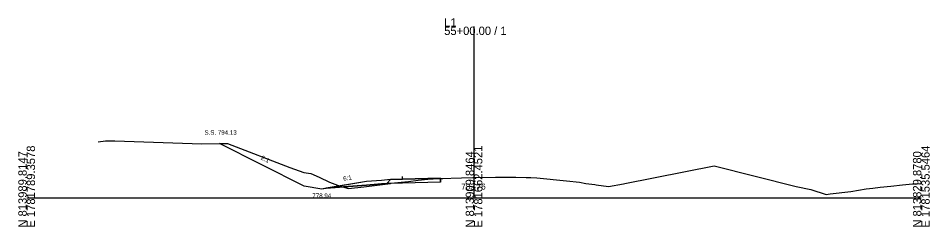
# Model space of a CAD drawing. Extents: x 5574 to 10203, y -10 to 9546.
# Drawn here: x 6597.2 to 6902.8, y 1990.3 to 2060.1 of the extents above; entities that cross this region are included whole.
import ezdxf

# ---------------------------------------------------------------- set-up
doc = ezdxf.new("R2010")
doc.units = 0
for name, color, linetype in [('Exist Cross Section Cell', 7, 'Continuous'), ('Exist XS Center Line Elevation Label', 7, 'Continuous'), ('Exist XS Ground Line', 7, 'Continuous'), ('Prop XS Ditch Slope Text', 7, 'Continuous'), ('Prop XS Ditch Standard Text', 7, 'Continuous'), ('Prop XS Dump Level', 7, 'Continuous'), ('Prop XS Earthwork Shape', 7, 'Continuous'), ('Prop XS EOT Tick Mark', 7, 'Continuous'), ('Prop XS Finish Grade', 7, 'Continuous'), ('Prop XS Finish Grade Earthwork', 7, 'Continuous'), ('Prop XS Finish Grade Paved Shoulder', 7, 'Continuous'), ('Prop XS Finish Grade Pavement', 7, 'Continuous'), ('Prop XS Hydro Typical Ditch Data', 7, 'Continuous'), ('Prop XS Pvmt Edge Slope', 7, 'Continuous'), ('Prop XS Side Slope Text', 7, 'Continuous'), ('Prop XS SS Elevation Text', 7, 'Continuous'), ('Prop XS Subgrade Earthwork', 7, 'Continuous'), ('Scratch_Level_3', 7, 'Continuous'), ('Scratch_Level_6', 7, 'Continuous')]:
    doc.layers.add(name, color=color, linetype=linetype)

msp = doc.modelspace()

# ---------------------------------------------------------------- linework, layer by layer
at = {"layer": 'Exist Cross Section Cell'}
for p, q in [((6750, 2000), (6750, 2057.31)), ((6600, 2000), (6750, 2000)), ((6750, 2000), (6900, 2000))]:
    msp.add_line(p, q, dxfattribs=at)
at = {"layer": 'Exist XS Ground Line'}
for p, q in [((6624.02, 2018.79), (6626.44, 2019.02)), ((6626.44, 2019.02), (6629.55, 2019.1)), ((6629.55, 2019.1), (6658.7, 2018.11)), ((6658.7, 2018.11), (6667.32, 2018.14)), ((6667.32, 2018.14), (6688.26, 2010.11)), ((6688.26, 2010.11), (6692.91, 2008.43)), ((6692.91, 2008.43), (6695.27, 2008.18)), ((6800.59, 2004.76), (6830.57, 2010.73)), ((6830.57, 2010.73), (6858.02, 2003.79)), ((6695.27, 2008.18), (6698.13, 2006.88)), ((6698.13, 2006.88), (6701.51, 2005.23)), ((6725.57, 2005.2), (6728.05, 2005.47)), ((6728.05, 2005.47), (6731.24, 2005.86)), ((6731.24, 2005.86), (6734.54, 2006.27)), ((6734.54, 2006.27), (6736.32, 2006.37)), ((6736.32, 2006.37), (6738.75, 2006.49)), ((6738.75, 2006.49), (6745.83, 2006.66)), ((6745.83, 2006.66), (6750, 2006.76)), ((6750, 2006.76), (6750.85, 2006.78)), ((6750.85, 2006.78), (6757.19, 2006.86)), ((6757.19, 2006.86), (6761.9, 2006.91)), ((6761.9, 2006.91), (6764.05, 2006.87)), ((6764.05, 2006.87), (6767.51, 2006.81)), ((6767.51, 2006.81), (6769.06, 2006.77)), ((6769.06, 2006.77), (6771.05, 2006.71)), ((6771.05, 2006.71), (6780.98, 2005.7)), ((6780.98, 2005.7), (6785.36, 2005.25)), ((6701.51, 2005.23), (6705.17, 2003.94)), ((6705.17, 2003.94), (6707.9, 2003.12)), ((6707.9, 2003.12), (6713.01, 2003.71)), ((6713.01, 2003.71), (6717.57, 2004.25)), ((6717.57, 2004.25), (6722.21, 2004.85)), ((6722.21, 2004.85), (6725.57, 2005.2)), ((6785.36, 2005.25), (6787.47, 2004.82)), ((6787.47, 2004.82), (6790.53, 2004.46)), ((6790.53, 2004.46), (6790.97, 2004.39)), ((6790.97, 2004.39), (6795.05, 2003.82)), ((6795.05, 2003.82), (6800.14, 2004.64)), ((6800.14, 2004.64), (6800.59, 2004.76)), ((6858.02, 2003.79), (6862.94, 2002.73)), ((6862.94, 2002.73), (6868.12, 2001.14)), ((6876.37, 2002.15), (6881.49, 2002.96)), ((6881.49, 2002.96), (6883.73, 2003.23)), ((6883.73, 2003.23), (6886.24, 2003.51)), ((6886.24, 2003.51), (6889.77, 2003.92)), ((6889.77, 2003.92), (6893.75, 2004.32)), ((6893.75, 2004.32), (6897.08, 2004.64)), ((6897.08, 2004.64), (6898.52, 2004.72)), ((6898.52, 2004.72), (6900, 2004.79)), ((6868.12, 2001.14), (6869.42, 2001.3)), ((6869.42, 2001.3), (6876.37, 2002.15))]:
    msp.add_line(p, q, dxfattribs=at)
at = {"layer": 'Prop XS Dump Level'}
msp.add_line((6738.76, 2006.54), (6726, 2006.28), dxfattribs=at)
msp.add_line((6738.76, 2006.54), (6726, 2006.28), dxfattribs=at)
at = {"layer": 'Prop XS Earthwork Shape'}
for points in [[(6705.17, 2003.94), (6706.2, 2003.63), (6700.4, 2003.17), (6699, 2002.94), (6693, 2003.94), (6664.61, 2018.13), (6667.32, 2018.14), (6688.26, 2010.11), (6692.91, 2008.43), (6695.27, 2008.18), (6698.13, 2006.88), (6701.51, 2005.23)], [(6722.05, 2004.83), (6722.21, 2004.85), (6725.57, 2005.2), (6728.05, 2005.47), (6731.24, 2005.86), (6734.54, 2006.27), (6736.32, 2006.37), (6738.75, 2006.49), (6738.76, 2006.49), (6738.76, 2005.24), (6726, 2004.92)], [(6713.01, 2003.71), (6717.57, 2004.25), (6722.05, 2004.83), (6722, 2004.83), (6720.72, 2004.79), (6719, 2004.66), (6714, 2004.26), (6706.2, 2003.63), (6707.9, 2003.12)]]:
    msp.add_lwpolyline(points, close=True, dxfattribs=at)
at = {"layer": 'Prop XS EOT Tick Mark'}
msp.add_line((6726, 2006.17), (6726, 2007.17), dxfattribs=at)
at = {"layer": 'Prop XS Finish Grade'}
for p, q in [((6714, 2005.44), (6700.4, 2003.17)), ((6719, 2005.84), (6714, 2005.44)), ((6722, 2006.08), (6719, 2005.84))]:
    msp.add_line(p, q, dxfattribs=at)
at = {"layer": 'Prop XS Finish Grade Earthwork'}
for p, q in [((6693, 2003.94), (6664.61, 2018.13)), ((6699, 2002.94), (6693, 2003.94)), ((6700.4, 2003.17), (6699, 2002.94))]:
    msp.add_line(p, q, dxfattribs=at)
at = {"layer": 'Prop XS Finish Grade Paved Shoulder'}
msp.add_line((6726, 2006.17), (6722, 2006.08), dxfattribs=at)
at = {"layer": 'Prop XS Finish Grade Pavement'}
msp.add_line((6738.76, 2006.49), (6726, 2006.17), dxfattribs=at)
at = {"layer": 'Prop XS Hydro Typical Ditch Data'}
for p, q in [((6693, 2003.94), (6664.61, 2018.13)), ((6714, 2005.44), (6699, 2002.94)), ((6699, 2002.94), (6693, 2003.94))]:
    msp.add_line(p, q, dxfattribs=at)
at = {"layer": 'Prop XS Pvmt Edge Slope'}
msp.add_line((6722, 2006.08), (6720.72, 2004.79), dxfattribs=at)
at = {"layer": 'Prop XS Subgrade Earthwork'}
for p, q in [((6738.76, 2005.24), (6738.76, 2006.49)), ((6714, 2004.26), (6700.4, 2003.17)), ((6719, 2004.66), (6714, 2004.26)), ((6720.72, 2004.79), (6719, 2004.66)), ((6722, 2004.83), (6720.72, 2004.79)), ((6726, 2004.92), (6722, 2004.83)), ((6738.76, 2005.24), (6726, 2004.92))]:
    msp.add_line(p, q, dxfattribs=at)
at = {"layer": 'Scratch_Level_3'}
for p, q in [((6714, 2005.44), (6700.4, 2003.17)), ((6719, 2005.84), (6714, 2005.44)), ((6722, 2006.08), (6719, 2005.84)), ((6720.72, 2004.79), (6722, 2006.08)), ((6700.4, 2003.17), (6714, 2004.26)), ((6714, 2004.26), (6719, 2004.66)), ((6719, 2004.66), (6720.72, 2004.79))]:
    msp.add_line(p, q, dxfattribs=at)
at = {"layer": 'Scratch_Level_6'}
for points in [[(6728.05, 2005.47), (6731.24, 2005.86), (6734.54, 2006.27), (6736.32, 2006.37), (6738.75, 2006.49), (6738.76, 2006.49), (6738.76, 2005.24), (6726, 2004.92), (6722.05, 2004.83), (6722.21, 2004.85), (6725.57, 2005.2)], [(6705.17, 2003.94), (6706.2, 2003.63), (6700.4, 2003.17), (6705.13, 2003.96)]]:
    msp.add_lwpolyline(points, close=True, dxfattribs=at)

# ---------------------------------------------------------------- texts
at = {"layer": 'Exist Cross Section Cell'}
for s, p in [('55+00.00 / 1', (6740, 2054.51)), ('L1', (6740, 2057.31))]:
    msp.add_text(s, height=2.8, dxfattribs=at).set_placement(p)
for s, p in [('N 813989.8147', (6600, 1990)), ('E 1781789.3578', (6602.8, 1990)), ('N 813909.8464', (6750, 1990)), ('E 1781662.4521', (6752.8, 1990)), ('N 813829.8780', (6900, 1990)), ('E 1781535.5464', (6902.8, 1990))]:
    msp.add_text(s, height=2.8, rotation=90, dxfattribs=at).set_placement(p)
at = {"layer": 'Exist XS Center Line Elevation Label'}
msp.add_text('782.76', height=2, dxfattribs=at).set_placement((6745.73, 2002.76))
at = {"layer": 'Prop XS Ditch Slope Text'}
msp.add_text('6:1', height=1.5, rotation=9.4623, dxfattribs=at).set_placement((6706.25, 2005.67))
at = {"layer": 'Prop XS Ditch Standard Text'}
msp.add_text('778.94', height=1.5, dxfattribs=at).set_placement((6695.78, 1999.94))
at = {"layer": 'Prop XS Dump Level'}
for s, height, p in [('Case4', 0.04, (6714, 2005.4)), ('Eop', 0.3, (6738.76, 2006.19))]:
    msp.add_text(s, height=height, dxfattribs=at).set_placement(p)
at = {"layer": 'Prop XS Side Slope Text'}
msp.add_text('2:1', height=1.5, rotation=333.4349, dxfattribs=at).set_placement((6678.39, 2012.92))
at = {"layer": 'Prop XS SS Elevation Text'}
msp.add_text('S.S. 794.13', height=1.5, dxfattribs=at).set_placement((6659.6, 2021.13))

doc.saveas('drawing.dxf')
